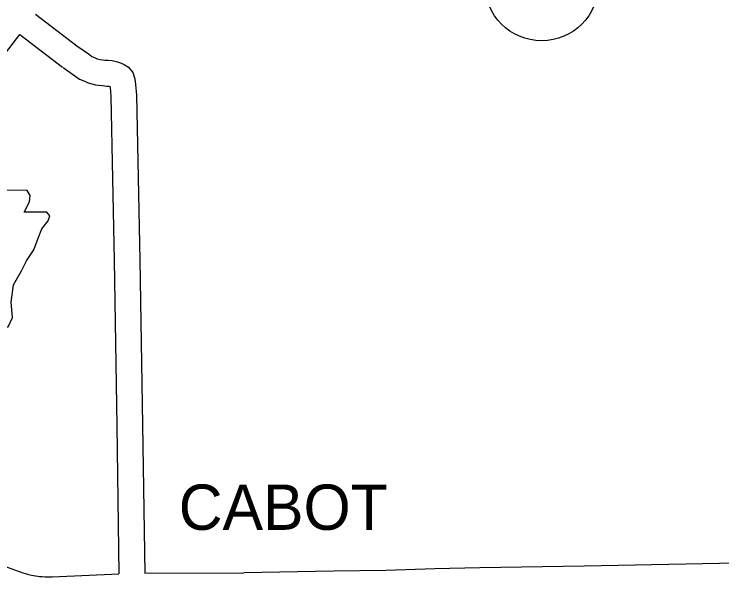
# Model space of a CAD drawing. Extents: x 1367863 to 1368197, y 380048 to 380261.
# Drawn here: x 1367891.07 to 1367905.41, y 380206.52 to 380217.92 of the extents above; entities that cross this region are included whole.
import ezdxf

# ---------------------------------------------------------------- set-up
doc = ezdxf.new("R2010")
doc.units = 0
for name, color, linetype in [('Level 10', 7, 'Continuous'), ('Level 21', 7, 'Continuous'), ('Level 27', 7, 'Continuous'), ('Level 6', 7, 'Continuous')]:
    doc.layers.add(name, color=color, linetype=linetype)

msp = doc.modelspace()

# ---------------------------------------------------------------- linework, layer by layer
at = {"layer": 'Level 10'}
for points in [[(1367891.506, 380217.925), (1367892.371, 380217.262)], [(1367878.711, 380208.994), (1367879.246, 380208.537), (1367879.335, 380208.483), (1367879.446, 380208.46), (1367879.517, 380208.465), (1367879.586, 380208.474), (1367879.703, 380208.516), (1367879.817, 380208.577), (1367882.84, 380210.657), (1367885.268, 380212.307), (1367888.361, 380214.452), (1367889.151, 380214.979), (1367889.29, 380215.089), (1367889.397, 380215.208), (1367889.544, 380215.389), (1367889.775, 380215.682), (1367891.186, 380217.512)], [(1367891.186, 380217.512), (1367892.053, 380216.847)], [(1367892.362, 380217.269), (1367892.597, 380217.105), (1367892.649, 380217.069), (1367892.698, 380217.049), (1367892.752, 380217.022), (1367892.818, 380217.005), (1367892.91, 380216.994), (1367892.975, 380216.989), (1367893.055, 380216.988), (1367893.164, 380216.961), (1367893.23, 380216.938), (1367893.3, 380216.902), (1367893.39, 380216.847), (1367893.474, 380216.744), (1367893.52, 380216.61), (1367893.534, 380216.498), (1367893.553, 380216.283), (1367893.621, 380212.939), (1367893.675, 380209.596), (1367893.717, 380206.591)], [(1367892.063, 380216.84), (1367892.3, 380216.675), (1367892.396, 380216.609), (1367892.481, 380216.573), (1367892.571, 380216.529), (1367892.722, 380216.491), (1367892.856, 380216.475), (1367892.949, 380216.466), (1367892.99, 380216.466), (1367893.013, 380216.461), (1367893.015, 380216.442), (1367893.032, 380216.254), (1367893.099, 380212.93), (1367893.153, 380209.588), (1367893.194, 380206.579)], [(1367914.023, 380206.934), (1367911.542, 380206.881), (1367909.666, 380206.86), (1367908.084, 380206.839), (1367905.025, 380206.781), (1367902.622, 380206.732), (1367900.509, 380206.697), (1367899.595, 380206.681), (1367898.605, 380206.648), (1367897.541, 380206.629), (1367895.723, 380206.595)], [(1367890.802, 380206.763), (1367891.251, 380206.597), (1367891.295, 380206.583), (1367891.321, 380206.575), (1367891.361, 380206.566), (1367891.421, 380206.551), (1367891.464, 380206.542), (1367891.502, 380206.536), (1367891.549, 380206.528), (1367891.589, 380206.525), (1367891.643, 380206.521), (1367891.699, 380206.516), (1367891.842, 380206.519), (1367893.194, 380206.579)], [(1367893.717, 380206.591), (1367895.727, 380206.595)]]:
    msp.add_lwpolyline(points, dxfattribs=at)
at = {"layer": 'Level 21'}
msp.add_lwpolyline([(1367888.685, 380214.353), (1367888.818, 380213.47), (1367888.759, 380212.129), (1367888.877, 380212.056), (1367889.098, 380212.056), (1367889.098, 380211.584), (1367890.954, 380211.584), (1367891.042, 380211.776), (1367891.013, 380212.085), (1367891.057, 380212.439), (1367891.219, 380212.718), (1367891.322, 380212.925), (1367891.469, 380213.146), (1367891.557, 380213.381), (1367891.631, 380213.573), (1367891.764, 380213.735), (1367891.793, 380213.838), (1367891.734, 380213.911), (1367891.278, 380213.911), (1367891.381, 380214.118), (1367891.395, 380214.25), (1367891.334, 380214.352)], close=True, dxfattribs=at)
at = {"layer": 'Level 27'}
msp.add_circle((1367901.76, 380218.535), 1.149, dxfattribs=at)

# ---------------------------------------------------------------- texts
at = {"layer": 'Level 6'}
msp.add_text('CABOT', height=0.9194, dxfattribs=at).set_placement((1367894.407, 380207.469))

doc.saveas('drawing.dxf')
